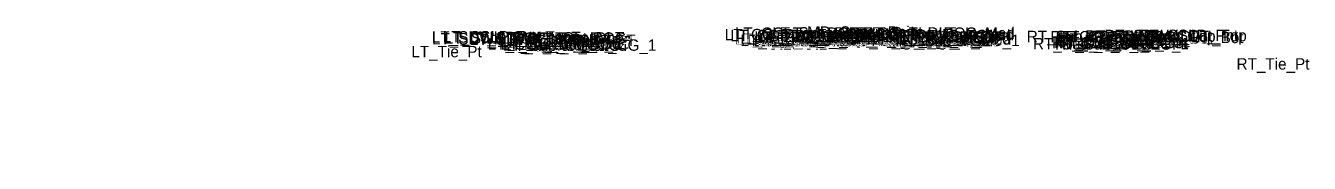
# Model space of a CAD drawing. Extents: x -26 to 4229, y -10 to 9523.
# Drawn here: x 0 to 225.1, y 4500 to 4524.1 of the extents above; entities that cross this region are included whole.
import ezdxf

# ---------------------------------------------------------------- set-up
doc = ezdxf.new("R2010")
doc.units = 0
doc.layers.add('Default', color=7, linetype='Continuous')

msp = doc.modelspace()

# ---------------------------------------------------------------- texts
at = {"layer": 'Default'}
for s, height, p in [('LT_SDWK_Out_Top', 2, (71.24, 4521.16)), ('LT_CSLP_Pnt', 2, (73.17, 4521.19)), ('LT_CG_Top_Face_Med', 2, (122.62, 4521.57)), ('LT_CG_Top_Gut_Med', 2, (123.6, 4521.4)), ('LT_CG_Top_BOC_Med', 2, (124.4, 4521.82)), ('LT_PV2_OEEOP', 2, (127.81, 4521.14)), ('LT_PV2_IEEOP', 2, (128.45, 4521.14)), ('LT_PV2_PGL', 2, (129.71, 4521.14)), ('LT_PV1_PGL', 2, (130.28, 4521.39)), ('LT_Sub_DLT_In', 2, (130.96, 4521.86)), ('MD_Crown Point', 2, (137.07, 4522.02)), ('RT_CG_Top_Face_Med', 2, (144.07, 4521.57)), ('RT_CG_Top_BOC_Med', 2, (144.34, 4521.82)), ('RT_CG_Top_Gut_Med', 2, (145.05, 4521.4)), ('RT_Sub_DLT_In', 2, (146.88, 4521.86)), ('RT_PV2_OEEOP', 2, (150.76, 4521.14)), ('RT_PV2_IEEOP', 2, (151.41, 4521.14)), ('RT_PV2_PGL', 2, (152.67, 4521.14)), ('RT_PV1_PGL', 2, (153.23, 4521.39)), ('RT_Sub_Trench_Out_DLT', 2, (175.59, 4521.23)), ('RT_CG_Top_Face', 2, (179.71, 4521.19)), ('RT_CG_Top_BOC', 2, (181.24, 4521.19)), ('RT_SDWK_In_Top', 2, (185.81, 4521.3)), ('RT_SDWK_Out_Top', 2, (189.19, 4521.4)), ('RT_CSLP_Pnt', 2, (195.13, 4521.43)), ('LT_SDWK_Out_Bot', 2, (71.27, 4520.83)), ('LT_Sub_Trench_Out_DLT', 2, (73.49, 4520.99)), ('LT_SDWK_In_Top', 2, (77.86, 4521.06)), ('LT_SDWK_In_Bot', 2, (77.89, 4520.73)), ('LT_CG1_Shelf_Out', 2, (81.05, 4519.92)), ('LT_CG_Top_Face', 2, (82.76, 4520.95)), ('LT_CG_Top_BOC', 2, (83.28, 4520.95)), ('LT_CG_Bot_BOC', 2, (83.31, 4519.93)), ('LT_Sub_OEOT_CG_1', 2, (83.72, 4519.73)), ('LT_CG_Top_Gut', 2, (83.74, 4520.45)), ('LT_Sub_OEOP', 2, (84.36, 4519.67)), ('LT_CG_Bot_IE', 2, (87.41, 4519.98)), ('LT_Sub_OEOT', 2, (87.58, 4519.69)), ('LT_PV2_OEOT', 2, (87.67, 4520.32)), ('LT_PV3_OEOT', 2, (87.67, 4520.07)), ('LT_PV1_OEOT', 2, (88.24, 4520.57)), ('LT_CG_Bot_BOC_Med', 2, (124.44, 4520.83)), ('LT_CG_Bot_IE_Med', 2, (124.56, 4520.8)), ('LT_Sub_IEOT_CG_1', 2, (125.37, 4520.55)), ('LT_Sub_OEEOP', 2, (127.71, 4520.51)), ('LT_PV3_OEEOP', 2, (127.81, 4520.89)), ('LT_Sub_IEEOP', 2, (128.36, 4520.51)), ('LT_CG1_Shelf_In', 2, (128.68, 4520.84)), ('LT_Sub_PGL', 2, (129.62, 4520.51)), ('LT_Sub_IEOP', 2, (131.51, 4520.6)), ('RT_CG_Bot_BOC_Med', 2, (144.37, 4520.83)), ('RT_CG_Bot_IE_Med', 2, (147.52, 4520.8)), ('RT_CG1_Shelf_In', 2, (147.62, 4520.84)), ('RT_Sub_IEOT_CG_1', 2, (148.32, 4520.55)), ('RT_Sub_IEOP', 2, (149.95, 4520.6)), ('RT_Sub_OEEOP', 2, (150.67, 4520.51)), ('RT_PV3_OEEOP', 2, (150.76, 4520.89)), ('RT_Sub_IEEOP', 2, (151.31, 4520.51)), ('RT_Sub_PGL', 2, (152.57, 4520.51)), ('RT_Sub_OEOT_CG_1', 2, (176.67, 4519.97)), ('RT_CG1_Shelf_Out', 2, (180, 4520.16)), ('RT_CG_Bot_IE', 2, (180.37, 4520.22)), ('RT_Sub_OEOT', 2, (180.53, 4519.93)), ('RT_PV2_OEOT', 2, (180.63, 4520.56)), ('RT_PV3_OEOT', 2, (180.63, 4520.31)), ('RT_CG_Top_Gut', 2, (180.69, 4520.69)), ('RT_PV1_OEOT', 2, (181.19, 4520.81)), ('RT_CG_Bot_BOC', 2, (181.27, 4520.17)), ('RT_Sub_OEOP', 2, (183.82, 4519.91)), ('RT_SDWK_In_Bot', 2, (185.84, 4520.97)), ('RT_SDWK_Out_Bot', 2, (189.22, 4521.07)), ('LT_Tie_Pt', 2, (67.65, 4518.59)), ('RT_Tie_Pt', 2, (212.38, 4516.43)), ('-', 0.0001, (0, 4500)), ('-', 0.0001, (0, 4500)), ('-', 0.0001, (0, 4500)), ('-', 0.0001, (0, 4500)), ('-', 0.0001, (0, 4500)), ('-', 0.0001, (0, 4500)), ('-', 0.0001, (0, 4500)), ('-', 0.0001, (0, 4500)), ('-', 0.0001, (0, 4500))]:
    msp.add_text(s, height=height, dxfattribs=at).set_placement(p)

doc.saveas('drawing.dxf')
